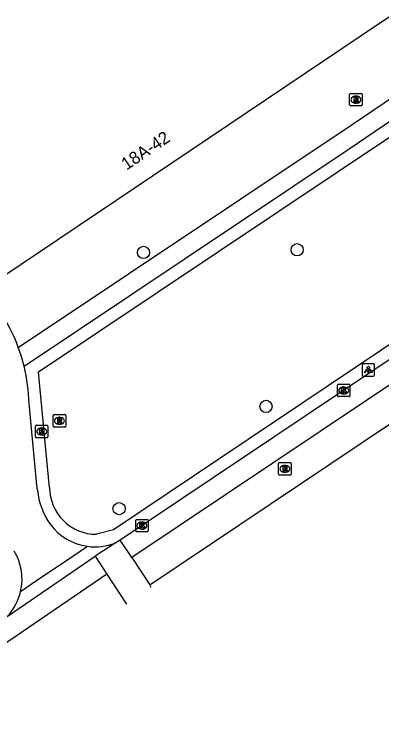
# Model space of a CAD drawing. Extents: x 158797 to 159887, y 384318 to 385255.
# Drawn here: x 159106.5 to 159136, y 384399.4 to 384456.6 of the extents above; entities that cross this region are included whole.
import ezdxf

# ---------------------------------------------------------------- set-up
doc = ezdxf.new("R2010")
doc.units = 0
for name, color, linetype in [('IMGEO_Boom', 7, 'Continuous'), ('IMGEO_Groenvoorziening', 7, 'Continuous'), ('IMGEO_Kolk', 7, 'Continuous'), ('IMGEO_Lichtpunt', 7, 'Continuous'), ('IMGEO_Pand', 7, 'Continuous'), ('IMGEO_Pand_nummerreeks', 7, 'Continuous'), ('IMGEO_Rijbaan_lokaal_gesloten', 7, 'Continuous'), ('IMGEO_Rijbaan_lokaal_open', 7, 'Continuous'), ('IMGEO_Rioolput', 7, 'Continuous'), ('IMGEO_Voetpad_open', 7, 'Continuous')]:
    doc.layers.add(name, color=color, linetype=linetype)

msp = doc.modelspace()

# ---------------------------------------------------------------- linework, layer by layer
at = {"layer": 'IMGEO_Boom'}
for centre in [(159129.245, 384437.674), (159116.923, 384437.457), (159126.746, 384425.111), (159114.957, 384416.909)]:
    msp.add_circle(centre, 0.489, dxfattribs=at)
at = {"layer": 'IMGEO_Groenvoorziening'}
for points in [[(159109.388, 384418.603), (159109.094, 384421.643), (159108.491, 384427.893), (159146.977, 384453.593)], [(159151.885, 384440.258), (159151.148, 384439.765), (159114.499, 384415.224), (159113.146, 384414.855)]]:
    msp.add_lwpolyline(points, dxfattribs=at)
msp.add_arc((159113.136, 384418.603), 3.748, 180.0048, 270.1479, dxfattribs=at)
at = {"layer": 'IMGEO_Kolk'}
for p, q in [((159132.48, 384425.965), (159132.48, 384426.817)), ((159132.555, 384426.891), (159133.407, 384426.891)), ((159133.481, 384426.817), (159133.481, 384425.965)), ((159132.991, 384426.111), (159132.966, 384426.111)), ((159132.968, 384426.671), (159132.993, 384426.671)), ((159133.407, 384425.891), (159132.555, 384425.891)), ((159116.294, 384415.122), (159116.294, 384415.974)), ((159116.369, 384416.048), (159117.221, 384416.048)), ((159116.782, 384415.828), (159116.807, 384415.828)), ((159117.295, 384415.974), (159117.295, 384415.122)), ((159116.805, 384415.268), (159116.78, 384415.268)), ((159117.221, 384415.048), (159116.369, 384415.048))]:
    msp.add_line(p, q, dxfattribs=at)
for points in [[(159132.48, 384425.965), (159132.48, 384426.817)], [(159132.555, 384426.891), (159133.407, 384426.891)], [(159133.481, 384426.817), (159133.481, 384425.965)], [(159132.801, 384426.591), (159132.924, 384426.591), (159132.924, 384426.44), (159133.054, 384426.591), (159133.218, 384426.591), (159133.072, 384426.44), (159133.225, 384426.191), (159133.073, 384426.191), (159132.988, 384426.355), (159132.924, 384426.288), (159132.924, 384426.191), (159132.801, 384426.191), (159132.801, 384426.591)], [(159133.407, 384425.891), (159132.555, 384425.891)], [(159116.294, 384415.122), (159116.294, 384415.974)], [(159116.369, 384416.048), (159117.221, 384416.048)], [(159117.295, 384415.974), (159117.295, 384415.122)], [(159116.615, 384415.748), (159116.738, 384415.748), (159116.738, 384415.597), (159116.868, 384415.748), (159117.032, 384415.748), (159116.886, 384415.597), (159117.039, 384415.348), (159116.887, 384415.348), (159116.802, 384415.512), (159116.738, 384415.445), (159116.738, 384415.348), (159116.615, 384415.348), (159116.615, 384415.748)], [(159117.221, 384415.048), (159116.369, 384415.048)]]:
    msp.add_lwpolyline(points, dxfattribs=at)
for centre, start, end in [((159132.557, 384426.815), 91.552, 178.448), ((159132.557, 384426.815), 91.552, 178.448), ((159133.405, 384426.815), 1.552, 88.448), ((159133.405, 384426.815), 1.552, 88.448), ((159132.557, 384425.967), 181.552, 268.448), ((159132.557, 384425.967), 181.552, 268.448), ((159133.405, 384425.967), 271.552, 358.448), ((159133.405, 384425.967), 271.552, 358.448), ((159116.371, 384415.972), 91.552, 178.448), ((159116.371, 384415.972), 91.552, 178.448), ((159117.219, 384415.972), 1.552, 88.448), ((159117.219, 384415.972), 1.552, 88.448), ((159116.371, 384415.124), 181.552, 268.448), ((159116.371, 384415.124), 181.552, 268.448), ((159117.219, 384415.124), 271.552, 358.448), ((159117.219, 384415.124), 271.552, 358.448)]:
    msp.add_arc(centre, 0.0765, start, end, dxfattribs=at)
for centre, major_axis, ratio, start_param, end_param in [((159132.967, 384426.391), (-0.387, 0.002), 0.722429, 4.712389, 7.853982), ((159132.992, 384426.391), (-0.39, 0.002), 0.717154, 1.570796, 4.712389), ((159116.781, 384415.548), (-0.387, 0.002), 0.722429, 4.712389, 7.853982), ((159116.806, 384415.548), (-0.39, 0.002), 0.717154, 1.570796, 4.712389)]:
    msp.add_ellipse(centre, major_axis=major_axis, ratio=ratio, start_param=start_param, end_param=end_param, dxfattribs=at)
at = {"layer": 'IMGEO_Lichtpunt'}
for p, q in [((159134.458, 384428.426), (159134.458, 384427.619)), ((159134.458, 384428.426), (159134.458, 384427.619)), ((159135.36, 384428.521), (159134.552, 384428.521)), ((159135.36, 384428.521), (159134.552, 384428.521)), ((159135.454, 384427.619), (159135.454, 384428.426)), ((159135.454, 384427.619), (159135.454, 384428.426)), ((159134.552, 384427.525), (159135.36, 384427.525)), ((159134.552, 384427.525), (159135.36, 384427.525))]:
    msp.add_line(p, q, dxfattribs=at)
for points in [[(159134.832, 384428.09), (159134.871, 384428.062), (159134.683, 384427.8), (159134.645, 384427.827), (159134.832, 384428.09)], [(159134.934, 384428.042), (159134.981, 384428.042), (159134.981, 384427.72), (159134.934, 384427.72), (159134.934, 384428.042)], [(159135.044, 384428.062), (159135.082, 384428.089), (159135.269, 384427.827), (159135.23, 384427.799), (159135.044, 384428.062)]]:
    msp.add_lwpolyline(points, dxfattribs=at)
msp.add_circle((159134.957, 384428.224), 0.0994, dxfattribs=at)
for centre, start, end in [((159134.552, 384428.426), 90, 180), ((159134.552, 384428.426), 90, 180), ((159135.36, 384428.426), 0, 90), ((159135.36, 384428.426), 0, 90), ((159134.552, 384427.619), 180, 270), ((159134.552, 384427.619), 180, 270), ((159135.36, 384427.619), 270, 0), ((159135.36, 384427.619), 270, 360)]:
    msp.add_arc(centre, 0.0946, start, end, dxfattribs=at)
at = {"layer": 'IMGEO_Pand'}
msp.add_lwpolyline([(159105.622, 384435.536), (159134.297, 384454.798), (159140.265, 384458.806), (159139.961, 384459.26)], dxfattribs=at)
at = {"layer": 'IMGEO_Rijbaan_lokaal_gesloten'}
for points in [[(159270.461, 384513.33), (159268.841, 384512.562), (159250.873, 384502.69), (159237.802, 384494.419), (159214.07, 384478.627), (159115.99, 384412.992)], [(159117.415, 384410.802), (159170.564, 384446.405), (159170.651, 384446.275), (159170.651, 384446.275)], [(159152.977, 384439.786), (159152.441, 384439.427), (159115.055, 384414.393)], [(159105.991, 384408.267), (159113.048, 384413.097)]]:
    msp.add_lwpolyline(points, dxfattribs=at)
at = {"layer": 'IMGEO_Rijbaan_lokaal_open'}
for points in [[(159108.404, 384418.385), (159108.367, 384418.769), (159108.226, 384420.231), (159107.732, 384425.348)], [(159114.655, 384414.147), (159113.048, 384413.097)], [(159115.055, 384414.393), (159114.655, 384414.147)], [(159115.99, 384412.992), (159115.055, 384414.393)], [(159107.06, 384410.273), (159108.337, 384411.145), (159111.25, 384413.104), (159112.416, 384413.889)], [(159113.048, 384413.097), (159113.987, 384411.669)], [(159115.99, 384412.992), (159117.415, 384410.802)], [(159113.987, 384411.669), (159096.03, 384399.42)], [(159113.987, 384411.669), (159115.546, 384409.253)], [(159117.539, 384410.592), (159117.415, 384410.802)]]:
    msp.add_lwpolyline(points, dxfattribs=at)
for centre, radius, start, end in [((159093.775, 384425.013), 13.962, 20.2439, 31.6487), ((159093.971, 384425.072), 13.758, 13.6769, 20.2951), ((159093.811, 384425.025), 13.925, 1.3303, 13.7102), ((159114.187, 384419.018), 5.817, 186.2511, 215.5893), ((159113.038, 384418.329), 4.483, 216.9634, 262.0244), ((159113.039, 384418.329), 4.483, 262.0144, 291.132), ((159102.795, 384411.256), 4.377, 347.0165, 30.9942), ((159102.8, 384411.255), 4.372, 316.8778, 347.0158)]:
    msp.add_arc(centre, radius, start, end, dxfattribs=at)
at = {"layer": 'IMGEO_Rioolput'}
for p, q in [((159133.458, 384449.283), (159133.458, 384450.135)), ((159133.533, 384450.209), (159134.385, 384450.209)), ((159134.459, 384450.135), (159134.459, 384449.283)), ((159133.946, 384449.989), (159133.971, 384449.989)), ((159134.385, 384449.209), (159133.533, 384449.209)), ((159133.969, 384449.429), (159133.944, 384449.429)), ((159109.749, 384424.454), (159110.601, 384424.454)), ((159109.674, 384423.528), (159109.674, 384424.38)), ((159110.162, 384424.234), (159110.187, 384424.234)), ((159110.675, 384424.38), (159110.675, 384423.528)), ((159108.249, 384422.675), (159108.249, 384423.527)), ((159108.324, 384423.601), (159109.176, 384423.601)), ((159108.737, 384423.381), (159108.762, 384423.381)), ((159109.25, 384423.527), (159109.25, 384422.675)), ((159110.601, 384423.454), (159109.749, 384423.454)), ((159110.185, 384423.674), (159110.16, 384423.674)), ((159108.76, 384422.821), (159108.735, 384422.821)), ((159109.176, 384422.601), (159108.324, 384422.601)), ((159127.761, 384419.674), (159127.761, 384420.526)), ((159127.836, 384420.6), (159128.688, 384420.6)), ((159128.762, 384420.526), (159128.762, 384419.674)), ((159128.272, 384419.82), (159128.247, 384419.82)), ((159128.249, 384420.38), (159128.274, 384420.38)), ((159128.688, 384419.6), (159127.836, 384419.6))]:
    msp.add_line(p, q, dxfattribs=at)
for points in [[(159133.458, 384449.283), (159133.458, 384450.135)], [(159133.533, 384450.209), (159134.385, 384450.209)], [(159134.459, 384450.135), (159134.459, 384449.283)], [(159134.047, 384449.907), (159133.795, 384449.909), (159133.795, 384449.509)], [(159133.795, 384449.509), (159133.919, 384449.509), (159133.919, 384449.671), (159133.93, 384449.671)], [(159133.973, 384449.828), (159133.919, 384449.828), (159133.919, 384449.747)], [(159133.919, 384449.747), (159133.971, 384449.747)], [(159133.977, 384449.642), (159134.048, 384449.509), (159134.188, 384449.509), (159134.123, 384449.635)], [(159134.385, 384449.209), (159133.533, 384449.209)], [(159109.749, 384424.454), (159110.601, 384424.454)], [(159109.674, 384423.528), (159109.674, 384424.38)], [(159110.263, 384424.152), (159110.011, 384424.154), (159110.011, 384423.754)], [(159110.011, 384423.754), (159110.135, 384423.754), (159110.135, 384423.916), (159110.146, 384423.916)], [(159110.189, 384424.073), (159110.135, 384424.073), (159110.135, 384423.992)], [(159110.135, 384423.992), (159110.187, 384423.992)], [(159110.193, 384423.887), (159110.264, 384423.754), (159110.404, 384423.754), (159110.339, 384423.88)], [(159110.675, 384424.38), (159110.675, 384423.528)], [(159108.249, 384422.675), (159108.249, 384423.527)], [(159108.324, 384423.601), (159109.176, 384423.601)], [(159108.838, 384423.299), (159108.586, 384423.301), (159108.586, 384422.901)], [(159109.25, 384423.527), (159109.25, 384422.675)], [(159110.601, 384423.454), (159109.749, 384423.454)], [(159108.586, 384422.901), (159108.71, 384422.901), (159108.71, 384423.063), (159108.721, 384423.063)], [(159108.764, 384423.22), (159108.71, 384423.22), (159108.71, 384423.139)], [(159108.71, 384423.139), (159108.762, 384423.139)], [(159108.768, 384423.034), (159108.839, 384422.901), (159108.979, 384422.901), (159108.914, 384423.027)], [(159109.176, 384422.601), (159108.324, 384422.601)], [(159127.761, 384419.674), (159127.761, 384420.526)], [(159127.836, 384420.6), (159128.688, 384420.6)], [(159128.762, 384420.526), (159128.762, 384419.674)], [(159128.35, 384420.298), (159128.098, 384420.3), (159128.098, 384419.9)], [(159128.098, 384419.9), (159128.222, 384419.9), (159128.222, 384420.062), (159128.233, 384420.062)], [(159128.276, 384420.219), (159128.222, 384420.219), (159128.222, 384420.138)], [(159128.222, 384420.138), (159128.274, 384420.138)], [(159128.28, 384420.033), (159128.351, 384419.9), (159128.491, 384419.9), (159128.426, 384420.026)], [(159128.688, 384419.6), (159127.836, 384419.6)]]:
    msp.add_lwpolyline(points, dxfattribs=at)
for centre, radius, start, end in [((159133.535, 384450.133), 0.0765, 91.552, 178.448), ((159133.535, 384450.133), 0.0765, 91.552, 178.448), ((159134.383, 384450.133), 0.0765, 1.552, 88.448), ((159134.383, 384450.133), 0.0765, 1.552, 88.448), ((159133.929, 384449.618), 0.0533, 26.0293, 88.6989), ((159133.955, 384449.936), 0.19, 274.7715, 282.9687), ((159133.979, 384449.732), 0.0964, 77.0061, 93.1865), ((159133.993, 384449.789), 0.0378, 276.6634, 79.6772), ((159134.046, 384449.797), 0.109, 350.3612, 89.416), ((159134.044, 384449.797), 0.112, 277.5842, 350.9817), ((159134.028, 384449.582), 0.108, 29.5134, 73.7905), ((159133.535, 384449.285), 0.0765, 181.552, 268.448), ((159133.535, 384449.285), 0.0765, 181.552, 268.448), ((159134.383, 384449.285), 0.0765, 271.552, 358.448), ((159134.383, 384449.285), 0.0765, 271.552, 358.448), ((159109.751, 384424.378), 0.0765, 91.552, 178.448), ((159109.751, 384424.378), 0.0765, 91.552, 178.448), ((159110.599, 384424.378), 0.0765, 1.552, 88.448), ((159110.599, 384424.378), 0.0765, 1.552, 88.448), ((159110.145, 384423.863), 0.0533, 26.0293, 88.6989), ((159110.171, 384424.181), 0.19, 274.7715, 282.9687), ((159110.195, 384423.977), 0.0964, 77.0061, 93.1865), ((159110.209, 384424.034), 0.0378, 276.6634, 79.6772), ((159110.262, 384424.042), 0.109, 350.3612, 89.416), ((159110.26, 384424.042), 0.112, 277.5842, 350.9817), ((159110.244, 384423.827), 0.108, 29.5134, 73.7905), ((159108.326, 384423.525), 0.0765, 91.552, 178.448), ((159108.326, 384423.525), 0.0765, 91.552, 178.448), ((159108.837, 384423.189), 0.109, 350.3612, 89.416), ((159109.174, 384423.525), 0.0765, 1.552, 88.448), ((159109.174, 384423.525), 0.0765, 1.552, 88.448), ((159109.751, 384423.53), 0.0765, 181.552, 268.448), ((159109.751, 384423.53), 0.0765, 181.552, 268.448), ((159110.599, 384423.53), 0.0765, 271.552, 358.448), ((159110.599, 384423.53), 0.0765, 271.552, 358.448), ((159108.72, 384423.01), 0.0533, 26.0293, 88.6989), ((159108.746, 384423.328), 0.19, 274.7715, 282.9687), ((159108.77, 384423.124), 0.0964, 77.0061, 93.1865), ((159108.784, 384423.181), 0.0378, 276.6634, 79.6772), ((159108.835, 384423.189), 0.112, 277.5842, 350.9817), ((159108.819, 384422.974), 0.108, 29.5134, 73.7905), ((159108.326, 384422.677), 0.0765, 181.552, 268.448), ((159108.326, 384422.677), 0.0765, 181.552, 268.448), ((159109.174, 384422.677), 0.0765, 271.552, 358.448), ((159109.174, 384422.677), 0.0765, 271.552, 358.448), ((159127.838, 384420.524), 0.0765, 91.552, 178.448), ((159127.838, 384420.524), 0.0765, 91.552, 178.448), ((159128.686, 384420.524), 0.0765, 1.552, 88.448), ((159128.686, 384420.524), 0.0765, 1.552, 88.448), ((159128.232, 384420.009), 0.0533, 26.0293, 88.6989), ((159128.258, 384420.327), 0.19, 274.7715, 282.9687), ((159128.282, 384420.123), 0.0964, 77.0061, 93.1865), ((159128.296, 384420.18), 0.0378, 276.6634, 79.6772), ((159128.349, 384420.188), 0.109, 350.3612, 89.416), ((159128.347, 384420.188), 0.112, 277.5842, 350.9817), ((159128.331, 384419.973), 0.108, 29.5134, 73.7905), ((159127.838, 384419.676), 0.0765, 181.552, 268.448), ((159127.838, 384419.676), 0.0765, 181.552, 268.448), ((159128.686, 384419.676), 0.0765, 271.552, 358.448), ((159128.686, 384419.676), 0.0765, 271.552, 358.448)]:
    msp.add_arc(centre, radius, start, end, dxfattribs=at)
for centre, major_axis, ratio, start_param, end_param in [((159133.945, 384449.709), (-0.387, 0.002), 0.722429, 4.712389, 7.853982), ((159133.97, 384449.709), (-0.39, 0.002), 0.717154, 1.570796, 4.712389), ((159110.161, 384423.954), (-0.387, 0.002), 0.722429, 4.712389, 7.853982), ((159110.186, 384423.954), (-0.39, 0.002), 0.717154, 1.570796, 4.712389), ((159108.736, 384423.101), (-0.387, 0.002), 0.722429, 4.712389, 7.853982), ((159108.761, 384423.101), (-0.39, 0.002), 0.717154, 1.570796, 4.712389), ((159128.248, 384420.1), (-0.387, 0.002), 0.722429, 4.712389, 7.853982), ((159128.273, 384420.1), (-0.39, 0.002), 0.717154, 1.570796, 4.712389)]:
    msp.add_ellipse(centre, major_axis=major_axis, ratio=ratio, start_param=start_param, end_param=end_param, dxfattribs=at)
at = {"layer": 'IMGEO_Voetpad_open'}
for points in [[(159106.875, 384429.844), (159133.657, 384447.711), (159146.329, 384456.299)], [(159107.339, 384428.325), (159133.348, 384445.716), (159147.152, 384455.106)]]:
    msp.add_lwpolyline(points, dxfattribs=at)

# ---------------------------------------------------------------- texts
at = {"layer": 'IMGEO_Pand_nummerreeks'}
msp.add_text('18A-42', height=1, rotation=33.8905, dxfattribs=at).set_placement((159115.559, 384444.018))

doc.saveas('drawing.dxf')
